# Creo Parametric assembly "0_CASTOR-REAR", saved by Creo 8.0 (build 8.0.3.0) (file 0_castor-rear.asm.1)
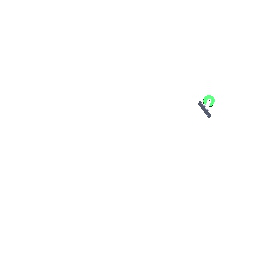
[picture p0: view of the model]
Units: millimeter Newton Second (mmNs); MM, TONNE, SECS

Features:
  1. datum plane "ADTM1"
  2. datum plane "ADTM2"
  3. datum plane "ADTM3"
  4. component "4_MOUNTING-PANEL"
  5. component "4_CASTORS"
